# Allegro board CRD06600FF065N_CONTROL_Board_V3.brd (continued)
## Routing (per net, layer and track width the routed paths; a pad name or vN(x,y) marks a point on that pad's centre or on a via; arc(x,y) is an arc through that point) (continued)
P_SCL: length 26.7
  ART03 w0.127: v1(46.74,41.78) 46.74,41.66 47.12,41.27 48.51,41.27 48.86,40.93 61.43,40.93 62.86,39.5 v1(64.44,39.5)
  BOTTOM w0.152: U32.6 R438.1 64.7,37.98 64.44,38.23 v1(64.44,39.5) ; U28.174 47.22,39.51 47.32,39.62 47.32,41.2 v1(46.74,41.78)
P_SDA: length 23.4
  ART03 w0.127: v1(46.71,40.64) 46.71,40.41 47.12,40.01 49.02,40.01 49.27,40.25 60.5,40.25 63.5,37.26 v1(63.5,36.83)
  BOTTOM w0.152: U32.5 64.14,36.2 v1(63.5,36.83) R437.1 ; v1(46.71,40.64) U28.173
P_WD_GREEN: length 12.6
  BOTTOM w0.152: U28.143 31.71,40.54 33.05,41.87 35.96,41.87 36.96,42.87 39.86,42.87 40.34,43.35 D102.2
P_WD_RED: length 14.4
  BOTTOM w0.152: U28.144 32.22,40.26 33.34,41.38 36.18,41.38 37.25,42.44 41.96,42.44 42.87,43.35 D103.2
PFC-FB: length 4
  BOTTOM w0.152: J2.23 7.12,45.22 R49.2
PFC-VO: length 4.7
  TOP w0.152: R579.2 5.58,45.22 J2.24
PFC_OCP: length 20.3
  TOP w0.152: R605.2 19.56,40.26 17.27,40.26 R606.2 16.51,40.76 16.51,44.45 J2.15
  BOTTOM w0.152: J2.15 16.51,44.45 14.48,44.45 13.97,43.94 13.97,42.55 15.88,40.64 15.88,39.07 16.08,38.86 D96.3
PFCCURBSAMP: length 81.3
  TOP w0.152: R435.1 55.88,9.65 v1(56.39,10.16)
  ART03 w0.127: v1(56.39,10.16) 55.8,10.74 52.02,10.74 49.4,8.13 24.87,8.13 21.29,11.71 16.57,11.71 13.08,15.2 13.08,37.97 16.41,41.3 16.41,44.55 J2.17
PWM1A: length 54.5
  TOP w0.152: U58.8 63.5,30.48 v1(62.23,31.75)
  ART03 w0.127: J2.11 24.13,46.99 30.88,46.99 31.65,46.23 31.65,44.93 31.88,44.69 31.88,41.15 34.29,38.73 34.29,36.7 34.92,36.07 48.77,36.07 50.8,34.04 50.8,33.02 51.4,32.42 52.03,32.42 52.7,31.75 56.39,31.75 56.9,32.26 58.21,32.26 58.71,31.75 v1(62.23,31.75)
PWM1AA: length 20
  TOP w0.152: v1(62.23,33.02) 63.5,31.75 U58.9 ; v1(51.44,33.28) 51.93,33.78 52.7,33.78 53.47,33.02 R414.2
  ART03 w0.127: v1(51.44,33.28) 51.93,33.78 52.89,33.78 53.5,33.18 59.08,33.18 59.85,32.41 61.62,32.41 v1(62.23,33.02)
  BOTTOM w0.152: v1(51.44,33.28) U28.8
PWM1B: length 48.6
  TOP w0.152: U58.10 63.5,33.02 63.5,33.05 63.52,33.05 v1(63.52,33.06)
  ART03 w0.127: J2.5 31.62,44.58 31.62,40.26 32.95,38.93 32.95,36.54 34.44,35.05 48.9,35.05 50.29,33.66 50.29,31.88 51.05,31.11 57.66,31.11 58.8,29.97 62.53,29.97 63.52,30.96 v1(63.52,33.06)
PWM1BB: length 19.7
  TOP w0.152: U58.11 v1(63.5,34.29) ; v1(52.45,33.27) 52.7,33.27 54.23,31.75 R415.2
  ART03 w0.127: v1(63.5,34.29) 62.94,33.73 62.94,32.97 62.38,32.41 62.19,32.41 61.91,32.13 59.18,32.13 58.55,32.77 53.34,32.77 52.83,33.27 v1(52.45,33.27)
  BOTTOM w0.152: U28.10 51.08,32.28 51.56,32.77 51.94,32.77 v1(52.45,33.27)
PWM1C: length 57.4
  TOP w0.152: v1(63.35,19.2) 63.83,19.68 65.12,19.68
  ART03 w0.127: v1(58.55,29.08) 58.55,29.72 57.53,30.73 54.48,30.73 53.59,29.84 51.64,29.84 49.66,31.83 49.66,33.15 49.02,33.78 47.75,33.78 47.01,34.53 34.27,34.53 32.47,36.34 32.47,37.86 30.48,39.84 30.48,41.26 29.21,42.53 29.21,44.45 J2.7
  BOTTOM w0.152: v1(63.35,19.2) 63.35,20.09 62.69,20.75 61.85,20.75 61.63,20.97 60.59,20.97 59.45,22.11 59.45,24.54 58.83,25.17 58.83,28.93 58.55,29.21 v1(58.55,29.08)
PWM1CC: length 31.7
  TOP w0.152: v1(62.23,21.59) 62.36,21.46 63.37,21.46 63.88,20.95 U59.9 ; R416.2 v1(51.94,29.21)
  BOTTOM w0.152: U28.22 51.05,26.28 51.31,26.54 51.31,28.09 51.82,28.6 51.82,29.08 v1(51.94,29.21) 52.45,29.72 52.45,31.01 54.12,32.67 56.84,32.67 56.87,32.64 57.91,32.64 59.43,31.12 59.43,25.48 60.2,24.71 60.2,22.3 60.91,21.59 v1(62.23,21.59)
PWM1D: length 53.2
  TOP w0.152: U59.10 63.88,22.23 63.63,21.97 62.87,21.97 v1(62.23,22.61)
  ART03 w0.127: v1(62.23,22.61) 60.88,23.95 57.1,23.95 53.77,27.28 51.82,27.28 51.38,27.71 51.38,27.72 49.23,29.87 47.46,29.87 44.02,33.32 34.12,33.32 31.37,36.07 31.37,37.72 30.99,38.1 28.57,38.1 26.75,39.93 26.75,44.37 J2.9
PWM1DD: length 33.7
  TOP w0.152: v1(63.37,22.61) 63.37,23.01 63.86,23.5 U59.11 ; R417.2 v1(48.26,25.4)
  BOTTOM w0.152: v1(48.26,25.4) 48.65,25.79 U28.23 51.22,25.79 51.46,26.02 52.31,26.02 52.59,26.3 52.59,28.96 52.83,29.2 52.83,30.91 53.92,32 55.12,32 55.88,31.24 57.66,31.24 59.11,29.79 59.11,25.37 59.84,24.64 59.84,22.11 60.69,21.27 61.74,21.27 61.95,21.06 62.84,21.06 63.37,21.59 v1(63.37,22.61)
REF1: length 16.3
  TOP w0.152: R226.1 C262.2 70.48,12.06 v1(71.12,12.7)
  BOTTOM w0.152: U56.1 72.39,10.06 72.23,9.9 71.37,9.9 71.12,10.15 U56.2 v1(71.12,12.7) 70.23,13.59 67.08,13.59 66.69,13.2 U37.4 66.69,10.3 C268.2
RLYCTRL1: length 20.6
  BOTTOM w0.152: J2.22 10.16,39.88 11.3,38.73 15.29,38.73 16.05,37.97 18.8,37.97 19.68,38.86 D97.3 22.61,38.86 23.21,38.26 23.21,37.12 23.54,36.79 U28.132
SR-PWM-A: length 27.8
  TOP w0.152: v1(62.1,23.97) 62.23,23.97 63.03,24.77 U59.12
  ART03 w0.127: J3.9 67.56,43.18 70.5,40.24 70.5,38.88 64.79,33.17 64.79,26.18 63.41,24.81 62.94,24.81 v1(62.1,23.97)
SR-PWM-AA: length 34.2
  TOP w0.152: R422.2 53.53,31.43 53.53,31.69 v1(52.96,32.26) ; U59.13 63.72,26.04 v1(63.26,25.58)
  BOTTOM w0.152: v1(63.26,25.58) 62.81,25.13 62.81,22.43 62.48,22.1 60.88,22.1 60.58,22.4 60.58,24.82 59.78,25.61 59.78,31.4 58.17,33.02 53.34,33.02 52.96,32.64 v1(52.96,32.26) 52.83,32.38 51.82,32.38 51.31,31.88 51.31,28.57 51.02,28.28 U28.18
SR-PWM-B: length 27.7
  TOP w0.152: U59.2 60.96,26.04 v1(62.23,27.3)
  ART03 w0.127: J3.10 65.95,44.36 65.95,42.95 67.15,41.75 68.12,41.75 70.06,39.81 70.06,39.24 64.19,33.37 64.19,30.28 62.23,28.32 v1(62.23,27.3)
SR-PWM-BB: length 29.3
  TOP w0.152: U59.1 v1(61.09,27.3) ; v1(53.34,38.1) 53.34,38.02 54.49,36.88 R423.2
  BOTTOM w0.152: v1(61.09,27.3) 61.67,27.89 61.67,31.29 58.8,34.16 58.8,39.55 57.05,41.3 54.84,41.3 53.24,39.7 53.24,38.2 v1(53.34,38.1) 53.06,37.82 51.71,37.82 50.68,36.79 U28.1
SR-PWM-C: length 28.3
  TOP w0.152: v1(63.5,27.3) 63.5,26.8 61.21,24.51 61.21,24 60.71,23.5 U59.4
  BOTTOM w0.152: J3.11 69.85,43.17 68.35,41.67 63.5,41.67 62.49,40.66 62.49,37.67 62.81,37.35 62.81,28 v1(63.5,27.3)
SR-PWM-CC: length 25.2
  TOP w0.152: v1(52.07,35.18) 51.89,35.18 51,34.29 R424.2 ; v1(61.09,25.53) 61.09,25.15 60.71,24.77 U59.3
  BOTTOM w0.152: v1(61.09,25.53) 60.45,26.16 60.45,30.27 60.45,30.27 60.45,30.69 60.45,30.69 60.45,31.87 58.24,34.09 58.24,36.5 57.78,36.96 53.06,36.96 52.67,36.57 52.67,35.78 v1(52.07,35.18) 51.96,35.28 U28.4
SR-PWM-D: length 31.7
  TOP w0.152: v1(63.36,24) 62.72,23.37 62.1,23.37 61.72,22.99 61.72,21.72 60.96,20.95 U59.6
  ART03 w0.127: v1(63.36,24) 63.36,24.03 66.03,26.71 66.03,33.3 70.22,37.49 70.85,37.49 71.09,37.74 71.09,44.61 69.98,45.72 J3.12
SR-PWM-DD: length 23.4
  TOP w0.152: U59.5 60.71,22.23 v1(61.09,22.61) ; v1(53.34,34.04) 53.59,34.29 R425.2
  BOTTOM w0.152: v1(61.09,22.61) 61.09,24.77 60.11,25.75 60.11,31.59 58.33,33.37 54.01,33.37 v1(53.34,34.04) 53.18,34.2 51.09,34.2 51,34.28 U28.6
TCK_P: length 8.6
  TOP w0.152: R407.2 R408.2 33.66,9.02 33.05,9.63 33.05,10.36 32.64,10.77 30.64,10.77 v1(29.86,11.54)
  BOTTOM w0.152: U28.81 30.22,11.82 29.94,11.54 v1(29.86,11.54)
TDI_P: length 18.2
  TOP w0.152: J5.3 27.92,3.2 27.92,5.18 28.44,5.7 29.2,5.7 v1(29.84,6.35) R405.2
  BOTTOM w0.152: v1(29.84,6.35) 30.38,5.82 32.23,5.82 32.71,6.29 32.71,9.43 33.03,9.74 33.03,10.37 32.22,11.18 U28.77
TDO_P: length 13.9
  TOP w0.152: R406.2 32.38,6.99 v1(31.75,6.35) 33.01,5.09 33.01,3.19 J5.7
  BOTTOM w0.152: U28.78 31.71,6.39 v1(31.75,6.35)
TMS_P: length 15.7
  TOP w0.152: R404.2 v1(26.04,6.35) 25.18,5.5 25.18,3.39 J5.1
  BOTTOM w0.152: v1(26.04,6.35) 29.24,9.56 29.24,10.44 29.67,10.87 30.07,10.87 30.71,11.51 U28.80
VAC_POLARITY+: length 43.4
  TOP w0.152: v1(64.77,7.49) 62.99,9.27 62.99,11.18 60.93,13.23 60.93,17.12 61.98,18.16 61.98,18.92 v1(62.23,19.18)
  BOTTOM w0.152: v1(62.23,19.18) 62.23,19.3 61.87,19.66 61.87,20.27 61.48,20.66 60.44,20.66 59.11,22 59.11,24.46 58.55,25.02 58.55,27.43 57.91,28.07 57.91,30.35 57.4,30.86 55.5,30.86 55.24,31.11 D86.3 53.72,31.11 53.21,30.61 53.21,26.16 52.83,25.78 52.83,24 52.11,23.28 U28.28 ; U36.4 64.78,7.58 64.77,7.57 v1(64.77,7.49)
VO1+: length 10.5
  BOTTOM w0.508: J4.11 79.88,44.32 79.88,41.91 80.39,41.4 82.93,41.4 R574.1
VO2+: length 3.8
  TOP w0.508: R573.1 88.27,41.27 J4.8
VP3.3A: length 16.3
  TOP w0.381: C550.2 v1(43.81,15.24) ; C521.1 v1(48.26,19.05)
  BOTTOM w0.254: U28.36 48.49,19.28 v1(48.26,19.05) ; U28.54 43.71,15.14 v1(43.81,15.24)
  BOTTOM w0.508: v1(73.41,13.34) 74.04,12.7 74.04,7.92 72.98,6.86 R589.2 R225.1 ; R590.1 61.97,14.73 v1(61.85,14.61)
  vias: v1(59.56,10.79) v1(60.58,10.79)
VP3.3D: length 157.9
  TOP w0.381: C540.1 26.67,16.63 v1(26.67,16.51) ; 63.88,0.76 48.39,0.76 47.11,2.03 R412.1 R411.1 ; C541.2 v1(27.94,15.24)
  TOP w0.508: C547.2 v1(39.37,15.24) ; C545.2 v1(34.92,15.24) ; J18.2 20.95,8.29 v1(20.95,9.84) C406.2 ; R407.1 35.73,7.5 36.07,7.83 36.07,10.03 v1(36.2,10.16) ; C523.2 44.32,36.96 v1(44.2,36.83) ; C520.1 v1(48.26,35.56) ; C524.2 v1(40.01,36.83) ; C529.2 29.84,37.08 v1(29.59,36.83) ; R405.1 v1(29.84,10.16) ; C546.2 v1(36.83,15.24) ; R540.1 5.59,21.82 v1(5.43,21.66) ; R327.2 31.11,40.64 ; R409.2 v1(31.11,10.16) ; v1(21.97,26.54) 21.97,27.3 21.34,27.94 R546.2 20.57,27.3 v1(20.57,26.54) ; v1(48.26,24.13) 48.26,23.16 48.56,22.86 C557.2 ; v1(53.21,36.2) 53.21,37.16 52.57,37.8 52.57,38.59 53.35,39.37 54.58,39.37 ; C539.1 v1(26.67,20.32) ; R598.1 77.91,8.41 J17.2 ; v1(12.7,39.37) 13.46,38.61 R604.1 R606.1 ; C533.1 26.16,32.38 v1(26.67,32.89) ; R404.1 v1(26.04,10.16) ; C528.2 v1(33.66,36.83) ; C542.2 v1(29.84,15.24) ; C555.2 v1(48.26,27.94) ; R537.2 11.66,34.41 ; R400.2 37.47,40.64 ; C553.2 v1(48.26,30.48) ; C536.1 v1(26.67,28.57) ; C531.1 v1(26.67,34.92) ; C538.1 v1(26.67,23.5) ; C552.1 v1(48.26,31.75) ; v1(34.92,36.83) C527.2 ; C544.2 v1(33.66,15.24) ; C537.1 v1(26.67,27.3) ; R406.1 v1(32.38,10.16) ; C534.1 v1(26.67,31.11)
  BOTTOM w0.254: v1(33.66,36.83) 33.71,36.89 U28.147 ; U28.3 48.49,35.79 v1(48.26,35.56) ; U28.72 34.71,15.03 v1(34.92,15.24) ; v1(26.67,34.92) 26.03,34.28 U28.127 ; U28.11 48.3,31.79 v1(48.26,31.75) ; U28.106 26.38,23.79 v1(26.67,23.5) ; U28.119 26.22,30.28 26.67,30.73 v1(26.67,31.11) 26.04,31.11 25.71,30.79 U28.120 ; U28.125 26.28,33.28 v1(26.67,32.89) ; U28.138 29.22,37.21 v1(29.59,36.83) ; v1(26.67,27.3) 26.19,27.79 U28.114 ; U28.88 26.71,15.2 v1(26.67,15.24) ; v1(26.67,16.51) 26.44,16.28 U28.91 ; v1(44.2,36.83) 44.22,36.85 U28.168 ; v1(26.67,20.32) 26.63,20.28 U28.99 ; v1(36.83,15.24) 36.71,15.12 U28.68 ; v1(26.67,28.57) 26.46,28.79 U28.116 ; U28.20 48.92,27.28 v1(48.26,27.94) ; U28.152 36.22,37.82 35.23,36.83 v1(34.92,36.83) ; U28.62 39.71,14.9 v1(39.37,15.24) ; U28.75 33.22,14.8 v1(33.66,15.24) ; U28.26 48.41,24.28 v1(48.26,24.13) ; v1(48.26,30.48) 48.95,29.79 U28.15 ; U28.82 29.71,15.11 v1(29.84,15.24) ; U28.159 39.71,37.12 v1(40.01,36.83)
  BOTTOM w0.381: v1(53.21,36.2) 54.54,36.2 55.5,35.23 55.5,34.29 55.81,33.98 D94.2
  BOTTOM w0.508: C396.1 68.2,33.14 v1(68.07,33.27) 67.94,33.4 67.94,35.72 ; v1(71.75,34.8) R502.1 ; R437.2 v1(63.5,40.64) ; D96.2 13.92,39.81 v1(13.79,39.68) ; R438.2 v1(65.41,40.64) ; v1(49.53,44.45) 49.21,44.77 D98.2 ; D95.2 55.81,38.42 55.49,38.74 v1(55.49,39.35) ; R505.1 v1(71.12,33.02) ; R439.2 v1(67.31,40.64) ; J17.2 78.11,8.22 C405.1 ; D104.2 v1(52.7,41.91) ; v1(18.67,39.68) 18.8,39.81 D97.2
  vias: v1(6.35,11.43) v1(6.35,10.16) v1(6.35,8.89) v1(7.62,11.43) v1(7.62,10.16) v1(7.62,8.89) v1(27.94,16.51) v1(29.84,16.51) v1(49.53,43.18) v1(49.53,41.91) v1(51.44,41.91) v1(53.98,41.91) v1(71.75,1.27) v1(73.03,1.27) v1(74.3,1.27)
VP+5V: length 28
  TOP w0.381: C494.1 53.77,27.94 53.34,27.51 53.34,26.67 53.66,26.35 U55.1 56.7,26.35 58.55,28.19 68.45,28.19 v1(69.22,28.96) ; R549.2 v1(70.48,35.56)
  TOP w0.508: R536.2 9.01,30.86 v1(9.02,30.86) ; R550.2 69.34,28.83 v1(69.22,28.96)
  BOTTOM w0.381: R544.2 v1(40.01,6.35)
  BOTTOM w0.508: v1(69.22,28.96) 69.85,28.32 R595.2 70.87,28.06 71.38,28.57 R594.2
  vias: v1(6.1,32.77) v1(6.1,31.62) v1(6.1,30.48) v1(7.74,30.86) v1(10.29,30.86) v1(11.3,30.86) v1(52.7,5.08) v1(53.98,5.08) v1(53.98,3.81)
VP-5V: length 85.8
  ART03 w0.127: v1(69.85,19.3) 70.32,18.83 70.32,18.07 69.54,17.3 66.65,17.3 63.32,20.62 60.73,20.62 59.03,22.33 56.67,22.33 55.4,23.6 51,23.6 48.56,26.04 47.68,26.04 42.09,31.62 33.45,31.62 29.36,35.71 28.04,35.71 27.18,36.58 24,36.58 23.37,37.21 23.37,40.77 21.56,42.57 21.56,46.45 20.94,47.07 14.05,47.07 J2.19
  BOTTOM w0.152: U45.4 64.14,21.88 64.36,22.1 68.32,22.1 68.96,21.46 68.96,20.7 69.15,20.51 C450.1 v1(69.85,19.3)
VS+5V: length 7.3
  TOP w0.381: v1(98.3,23.75) 97.91,24.13 R492.2 ; v1(95.89,23.75) 95.89,23.4 95.61,23.12 R493.1 ; R496.1 v1(92.59,34.42)
  TOP w0.508: R507.1 v1(97.91,32.26)
  BOTTOM w0.381: R592.2 v1(88.9,20.95)
  BOTTOM w0.508: R593.2 91.87,26.04 v1(92.53,26.7)
VS+15V: length 24.8
  ART03 w0.508: v1(92.71,32.38) 91.44,32.38 88.9,34.92 v1(88.9,35.56) 91.44,38.1 v1(91.56,38.1) 92.94,38.1 95.29,40.45 95.29,44.41 J4.1
  BOTTOM w0.508: R503.1 91.69,32.89 92.2,32.89 v1(92.71,32.38) ; R569.1 v1(88.9,35.56) ; R597.1 v1(91.56,38.1) R500.1
VS+15V_U48: length 16.6
  ART03 w0.508: v1(90.17,38.1) 89.92,38.1 88.14,36.32 88.14,30.48 v1(88.9,29.72)
  BOTTOM w0.508: v1(90.17,38.1) 90.05,38.22 R597.2 ; U48.8 93.34,29.72 93.09,29.46 92.08,29.46 91.44,30.1 C566.1 C462.1 89.28,30.1 v1(88.9,29.72)
X1: length 9.1
  BOTTOM w0.254: Y1.1 17.62,33.08 20.13,33.08 C371.2 21.2,32.9 R221.1 21.82,32.28 U28.123
X2: length 9.3
  BOTTOM w0.254: Y1.2 18.44,31.24 C254.2 21.34,31.24 R221.2 21.64,30.99 21.94,31.28 U28.121
XRS: length 28
  TOP w0.508: v1(21.72,33.78) 21.71,33.78 C519.1 21.71,31.24 R546.1 20.1,30.74 19.82,30.46 19.82,27.43 15.89,23.5 R541.1 10.29,23.5 10.29,24.43 11.18,25.32 11.18,27.74 10.92,28 R547.1
  BOTTOM w0.254: v1(21.72,33.78) 22.35,33.15 23.37,33.15 23.73,32.79 U28.124
N16777869: length 10.1
  TOP w0.152: J5.11 J5.9 35.54,3.19 35.54,5.41 35.24,5.71 34.04,5.71 33.66,6.1 R408.1
N16779815: length 3.6
  TOP w0.152: v1(30.66,36.83) 31.11,37.29 R327.1
  BOTTOM w0.152: v1(30.66,36.83) 29.71,37.77 U28.139
N16809513: length 6.4
  TOP w0.152: J5.5 30.5,3.15 30.5,6.3 31.11,6.91 R409.1
N16810933: length 3.9
  TOP w0.152: R412.2 42.55,2.54 J5.13
N16810951: length 3.9
  TOP w0.152: J5.14 42.55,3.81 R411.2
N16824215: length 5.1
  TOP w0.152: R436.1 R435.2 R433.2 R434.1 C395.1
N16833081: length 2
  BOTTOM w0.152: R443.1 39.71,45.55 D102.1
N16833084: length 2
  BOTTOM w0.152: R444.1 44.16,45.21 D103.1
N16833087: length 2
  BOTTOM w0.152: D104.1 52.36,45.21 R445.1
N16835391: length 24.3
  TOP w0.152: v1(61.85,13.46) 61.85,12.95 63.5,11.3 63.5,9.53 64.77,8.26 J17.1
  BOTTOM w0.152: J17.1 C407.1 R446.1 ; R447.1 v1(61.85,13.46)
N16836592: length 57.5
  TOP w0.152: v1(27.94,17.78) 27.26,17.1 27.26,17.09 27.26,16.12 26.91,15.78 25.63,15.78 24.7,14.85 18.26,14.85 17.45,14.03 17.45,11.61 17.75,11.31 C409.1 R448.1 19.68,9.53 J18.1
  ART03 w0.127: v1(61.09,18.41) 59.87,18.41 57.91,20.37 49.63,20.37 49.31,20.69 46.49,20.69 44.32,18.52 28.68,18.52 v1(27.94,17.78)
  BOTTOM w0.152: R449.1 v1(61.09,18.41)
N16848574: length 4
  BOTTOM w0.381: U43.2 R482.2 C446.1
N16848598: length 4.6
  BOTTOM w0.381: R593.1 C445.2 89.41,27.3 88.14,26.04 U43.1
N16848614: length 6.9
  TOP w0.508: v1(74.93,25.4) 75.44,24.89 C447.2
  BOTTOM w0.381: v1(74.93,25.4) 75.56,26.04 75.82,26.04 ; 75.82,26.04 U43.8 ; 75.82,26.04 75.69,26.16 75.69,26.92 74.04,28.57 R594.1
N16848642: length 2.8
  BOTTOM w0.152: R483.1 U43.7
N16848644: length 12.7
  TOP w0.152: v1(71.12,23.62) 70.99,23.62 v1(66.8,19.43)
  BOTTOM w0.152: v1(71.12,23.62) 72.26,24.77 R483.2 R484.2 C448.2 ; v1(66.8,19.43) 65.91,19.43 65.41,19.94 U45.3
N16848814: length 2.8
  BOTTOM w0.152: 76.54,23.5 R485.1
N16848816: length 10.7
  TOP w0.152: v1(71.12,22.61) 71,22.48 C449.1 70.74,20.45 68.85,20.45 v1(67.77,19.37)
  BOTTOM w0.152: U45.2 66.67,20.17 66.86,19.98 67.16,19.98 v1(67.77,19.37) ; R485.2 72.26,23.5 71.37,22.61 v1(71.12,22.61) R486.1
N16848832: length 38.8
  TOP w0.152: v1(73.66,19.05) 72.52,20.19 C449.2 ; v1(57.63,12.04) 57.63,13.16 57,13.79 56.82,13.79 R487.1
  ART03 w0.127: v1(57.63,12.04) 57.63,10.97 58.45,10.16 60.93,10.16 61.95,11.18 72.85,11.18 74.83,13.16 74.83,17.88 v1(73.66,19.05)
  BOTTOM w0.152: 67.94,20.79 67.94,20.19 69.34,18.8 70.33,18.8 71.12,19.58 R486.2 72.51,20.2 v1(73.66,19.05)
N16848970: length 3.4
  BOTTOM w0.152: U44.6 96.52,20.5 96.22,20.19 95.5,20.19 95.25,20.45 U44.7
N16848978: length 9.7
  TOP w0.152: C454.1 R488.2 C453.2 R489.2 R492.1 96.4,24.25 v1(96.9,23.75)
  BOTTOM w0.152: U44.3 96.52,24.03 96.8,23.75 v1(96.9,23.75)
N16848994: length 10.6
  TOP w0.152: R494.2 93.07,24.64 v1(92.71,24.99) 91.97,24.25 R491.1 C455.1 ; R494.2 93.47,24.76 C454.2 ; R494.2 R493.2
  BOTTOM w0.152: U44.2 95.25,25.66 94.59,24.99 v1(92.71,24.99)
N16849016: length 4.4
  BOTTOM w0.152: U44.8 93.98,22.07 93.83,22.23 C457.1 R592.1
N16851028: length 3.3
  BOTTOM w0.152: U45.6 65.41,27.15 65.56,27.3 66.52,27.3 66.67,27.15 U45.7
N16851046: length 4.3
  BOTTOM w0.152: C451.1 R595.1 69.21,26.55 68.83,26.92 68.2,26.92 67.94,26.67 67.94,26.2
N16853569: length 5.3
  TOP w0.152: v1(95.89,34.29) 95.76,34.41 R495.2 C458.1 C460.1
  BOTTOM w0.152: U48.3 v1(95.89,34.29)
N16853931: length 10.1
  TOP w0.152: v1(94.61,34.29) 94.1,34.8 R496.2 C459.1 R497.1 94.1,38.66 94.51,39.07 96.82,39.07 97.28,38.61 C460.2
  BOTTOM w0.152: U48.2 v1(94.61,34.29)
N16853972: length 4.8
  BOTTOM w0.152: U48.1 93.34,34.42 92.71,33.78 92.07,33.78 R499.1 R569.2
N16854569: length 3.4
  BOTTOM w0.152: R500.2 89.03,36.83 88.39,36.2 U60.1
N16855013: length 10
  TOP w0.152: C466.2 93.85,31.49 93.85,31.88 94.74,32.77 95.89,32.77 v1(96.39,32.26) 96.4,32.26 R507.2 C467.1 R508.1
  BOTTOM w0.152: U48.5 97.16,31.5 v1(96.39,32.26)
N16855828: length 6
  TOP w0.152: v1(95.38,32.26) 94.99,31.87 C466.1 C465.1 R506.2
  BOTTOM w0.152: v1(95.38,32.26) 95.89,31.75 U48.6
N16855912: length 3.5
  BOTTOM w0.152: U61.2 87.86,28.57 88.29,28.14 89.61,28.14 R510.2
N16855916: length 3.9
  BOTTOM w0.152: U61.1 88.14,31.11 R503.2
N16860426: length 79.7
  TOP w0.152: C472.1 R598.2 ; C472.1 C471.1 ; C472.1 75.63,12.7 v1(75.25,12.32)
  ART03 w0.127: v1(75.25,12.32) 73.75,10.82 62.18,10.82 61.21,9.86 58.37,9.86 56.79,11.43 52.07,11.43 51.56,10.92 50.29,10.92 49.12,12.09 48.26,12.09 45.69,9.53 25.91,9.53 21.97,13.46 21.97,13.97 18.29,17.65 18.29,23.37 v1(19.05,24.13)
  BOTTOM w0.152: U53.1 75.44,11.43 75.25,11.62 v1(75.25,12.32) ; v1(19.05,24.13) R514.1 R515.1
N16860580: length 10.1
  TOP w0.508: C473.1 C475.1 C474.1 R516.2 90.32,12.04 90.83,12.04 91.31,11.56 v1(91.44,11.56)
  BOTTOM w0.508: v1(91.44,11.56) 91.31,11.43 U53.8
N16860640: length 9.7
  TOP w0.152: v1(84.45,13.97) 85.72,15.24 D112.1 D110.2
  BOTTOM w0.152: T1.2 U53.7 v1(84.45,13.97)
N16861242: length 8.5
  BOTTOM w0.152: T1.3 97.24,13.97 94.74,11.47 R517.1 94.74,8.73 J11.2
N16861249: length 9.2
  TOP w0.152: D113.2 D114.1 v1(84.45,16.51)
  BOTTOM w0.152: T1.1 U53.6 v1(84.45,16.51)
N16861268: length 11.3
  BOTTOM w0.152: J11.1 93.22,8.77 R517.2 93.22,11.89 97.84,16.51 T1.4
N16861373: length 4.3
  TOP w0.381: D111.2 90.77,14.61 90.3,14.61 89.66,15.24 D112.2 D114.2
N16866679: length 36.2
  TOP w0.152: R528.1 C488.1 R58.2 R600.1 50.16,12.06 v1(50.8,11.43)
  ART03 w0.127: v1(57.15,19.68) 57.07,19.61 46.28,19.61 44.45,17.78 43.18,17.78 41.4,16 41.4,13.97 42.8,12.58 49.65,12.58 v1(50.8,11.43)
  BOTTOM w0.152: R529.1 56.13,19.68 v1(57.15,19.68)
N16866735: length 5.1
  TOP w0.152: R531.1 R578.2 R530.1 C490.1 R601.1
N16867200: length 4.5
  TOP w0.152: R532.2 C492.1 R533.1 56.52,20.2 R534.1
N16867335: length 3.2
  TOP w0.152: R532.1 53.34,22.98 53.14,23.19 53.14,24.23 53.36,24.45 U55.2
N16868074: length 5.2
  TOP w0.152: R230.2 C264.1 ; R230.2 R229.2 ; R230.2 v1(64.14,11.81)
  BOTTOM w0.152: U36.2 v1(64.14,11.81)
N16868076: length 2.6
  TOP w0.152: R229.1 65.41,15.24 v1(64.77,15.88)
  BOTTOM w0.152: v1(64.77,15.88) 65.39,15.25 U37.1
N16868126: length 5.9
  BOTTOM w0.381: U36.5 63.49,7.51 63.5,7.49 63.5,6.47 R591.1 62.48,6.35 61.59,7.24 C265.2
N16868143: length 11.6
  TOP w0.508: C266.2 72.51,13.46 v1(73.66,14.61)
  BOTTOM w0.381: U56.8 72.39,16.13 73.66,14.86 v1(73.66,14.61) 72.77,13.72 72.77,12.95 73.28,12.45 73.28,9.27 72.39,8.38 R589.1
N16868206: length 10.2
  TOP w0.152: C495.2 71,16.36 70.26,15.62 R602.2 69.85,14.78 70.03,14.61 v1(71.12,14.61) 71.5,14.61 72.01,15.11 R535.1
  BOTTOM w0.152: U56.6 69.85,16.13 71.12,14.86 v1(71.12,14.61)
N16868218: length 18.5
  TOP w0.152: v1(72.39,14.61) 72.77,14.99 72.77,16.86 72.49,17.14 R535.2 72.01,18.16 C495.1
  BOTTOM w0.152: U56.7 71.12,16.15 72.39,14.88 v1(72.39,14.61) 71.84,14.06 67.38,14.06 66.69,14.74 U37.3 66.69,15.25 67.44,16 67.44,18.16 67.19,18.41 R524.1
N16868269: length 7.6
  TOP w0.152: R226.2 C262.1 67.82,14.48 v1(67.94,14.61) 67.94,14.99 R603.2
  BOTTOM w0.152: v1(67.94,14.61) 68.58,15.24 U56.5
N16868287: length 5.3
  BOTTOM w0.152: R225.2 C267.2 ; C267.2 R224.1 ; C267.2 U56.3
N16900365: length 4.1
  TOP w0.508: R537.1 R538.2 8.76,32.9 7.93,33.72 Q1.1
N16900541: length 7.3
  TOP w0.508: v1(8.4,27.46) 8.4,27.92 C505.1 7.5,28.82 R536.1 6.99,30.36 Q1.3
  BOTTOM w0.381: v1(8.4,27.46) 8.58,27.64 U57.7
N16908509: length 4.6
  TOP w0.508: v1(7.75,24.51) 7.41,24.51 7.11,24.2 R540.2 R541.2
  BOTTOM w0.381: v1(7.75,24.51) 7.93,24.33 U57.19
N16911091: length 2.6
  BOTTOM w0.508: U37.5 64.88,12.97 64.64,13.21 C263.2 R590.2
N16917336: length 18.7
  BOTTOM w0.152: R525.1 57.78,27.43 58.27,26.95 58.27,24.81 58.83,24.26 58.83,21.82 60.26,20.38 61.3,20.38 61.59,20.09 61.59,19.09 62.02,18.67 64.14,18.67 64.89,17.91 C483.1 65.15,17.14 65.4,16.89 65.41,16.89 R524.2
N16935004: length 2.7
  TOP w0.508: v1(9.41,27.47) 9.4,27.48 R547.2
  BOTTOM w0.381: v1(9.41,27.47) 9.23,27.65 U57.8
N16936023: length 9.3
  BOTTOM w0.152: U28.59 41.22,11.37 40.58,10.73 40.58,9.59 R544.1 C518.1 38.73,9.04 37.95,9.82 ZD3.2 37,9.82 R545.2
N17022031: length 6.6
  TOP w0.152: C561.1 R549.1 C562.1 C560.1 U58.14
N17025421: length 6.5
  TOP w0.152: C564.1 C565.1 C563.1 R550.1 U59.14
N17045637: length 3.4
  BOTTOM w0.152: R499.2 89.03,34.29 88.39,33.66 86.94,33.66
N17046827: length 4.5
  BOTTOM w0.152: R510.1 94.11,28.57 94.61,29.08 U48.7
N17096901: length 14.1
  TOP w0.381: R488.1 93.46,27.32 91.55,27.32 C237.2 R133.1 90.14,27.4 90.14,35.46 R573.2
N17102058: length 27.9
  TOP w0.152: R506.1 92.86,28.57 91.85,29.59 91.85,32.44 92.86,33.45 96.06,33.45 96.52,33.91 96.52,34.08 96.52,34.08 96.52,34.67 96.93,35.08 96.93,35.21 R495.1 v1(98.42,35.56)
  BOTTOM w0.152: R574.2 87.76,39.4 88.87,40.51 93.09,40.51 94.99,38.61 C594.1 R575.1 97.69,38.61 97.92,38.38 97.92,36.07 v1(98.42,35.56)
N17145225: length 8.6
  BOTTOM w0.152: R599.2 44.45,7.5 44.9,7.94 44.9,8.19 C595.1 45.08,9.65 44.87,9.65 44.45,10.08 44.45,10.41 44.2,10.67 43.81,10.67 43.18,11.3 43.18,11.94 42.71,12.4 U28.56
N17156215: length 75.3
  TOP w0.152: v1(38.73,6.35) 38.73,8.13 39.62,9.01 R601.2 ; v1(5.71,41.91) 5.21,42.41 R579.1
  ART03 w0.127: v1(5.71,41.91) 8.38,41.91 8.89,42.42 8.89,43.56 9.58,44.25 13.51,44.25 13.98,43.78 13.98,40.61 13.23,39.86 13.23,38.94 12.7,38.42 12.7,14.89 16.48,11.11 21.03,11.11 24.52,7.62 37.47,7.62 v1(38.73,6.35)
N17156241: length 92
  TOP w0.152: v1(48.84,11.58) 48.84,13.56 49.38,14.09 R600.2
  ART03 w0.127: v1(5.71,43.18) 7.17,44.63 13.39,44.63 13.97,45.21 13.97,46.1 14.68,46.81 18.21,46.81 18.92,46.1 18.92,41.53 13.84,36.45 13.84,16.76 17.65,12.95 21.46,12.95 25.4,9.02 45.77,9.02 48.34,11.58 v1(48.84,11.58)
  BOTTOM w0.152: v1(5.71,43.18) 4.95,42.41 R49.1
N17158559: length 52.1
  TOP w0.152: v1(27.43,37.47) 27.3,37.33 R16.2 ; R603.1 68.2,18.03 v1(68.2,18.29)
  ART03 w0.127: v1(68.2,18.29) 67.14,18.29 63.34,22.09 60.57,22.09 58.98,23.67 56.67,23.67 54.33,26.01 51.66,26.01 49.05,28.62 47.34,28.62 43.21,32.76 33.92,32.76 30.1,36.58 30.1,37.21 29.84,37.47 v1(27.43,37.47)
N17158583: length 56.6
  TOP w0.152: R572.2 24.13,37.33 v1(24.38,37.59) ; R602.1 69.85,18.03 v1(69.6,18.29)
  ART03 w0.127: v1(24.38,37.59) 25.02,36.96 27.43,36.96 28.18,36.21 29.71,36.21 33.7,32.22 42.55,32.22 47.41,27.36 48.66,27.36 51.94,24.08 55.55,24.08 57,22.63 59.46,22.63 61.09,21.01 63.7,21.01 67.06,17.65 68.96,17.65 v1(69.6,18.29)
N16779431153: length 3.1
  TOP w0.152: R400.1 v1(37.47,36.83)
  BOTTOM w0.152: v1(37.47,36.83) 37.22,37.08 U28.154

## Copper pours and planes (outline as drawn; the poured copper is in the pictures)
AGND on TOP (solid shape): 72.03,9.87 72.03,8.89 71.73,8.59 64.93,8.59 64.39,9.13 64.39,9.91 64.64,10.16 71.74,10.16
AGND on TOP (solid shape): 72.03,7.75 72.03,6.84 71.61,6.42 66.36,6.42 65.79,6.99 65.79,7.62 65.79,7.62 65.79,7.87 65.84,7.92 71.86,7.92
AGND on TOP (solid shape): 43.45,29.63 43.45,24.1 41.65,22.3 38.9,22.3 37.89,21.29 33.32,21.29 31.64,22.97 31.64,31.9 32.32,32.58 40.5,32.58
AGND on TOP (solid shape): 14.89,15.06 14.89,10.29 15.4,9.78 15.4,3.67 15.37,3.64 15.37,1.09 14.85,0.57 0.93,0.57 0.59,0.91 0.59,11.42 0.95,11.78 3.91,11.78 4.24,11.45 4.24,8.37 3.8,7.93 2.32,7.93 1.47,7.08 1.47,2.91 2.42,1.97 10.44,1.97 11.73,3.25 11.73,15.06 12.1,15.43 14.52,15.43
AGND on TOP (solid shape): outline of 190 points within 11.83,24.07 23.18,37.72
AGND on BOTTOM (solid shape): 43.19,31.06 43.19,21.89 42.1,20.8 32.22,20.8 31.23,21.79 31.23,31.28 31.85,31.9 42.35,31.9
AGND on BOTTOM (solid shape): 53.94,2.79 53.94,0.69 53.81,0.56 45.01,0.56 44.86,0.71 44.86,1.77 45.02,1.93 48.44,1.93 48.86,1.51 52.06,1.51 52.39,1.84 52.39,2.83 52.53,2.97 53.76,2.97
AGND on BOTTOM (solid shape): 61.82,2.52 65.34,2.52 65.68,2.86 70.05,2.86 70.24,2.66 70.24,1.12 69.94,0.82 56.94,0.82 56.65,1.11 56.65,2.28 56.87,2.5 58.86,2.5 59.22,2.86 61.48,2.86
AGND on BOTTOM (solid shape): 82.1,19.81 82.1,0.85 81.82,0.57 75.45,0.57 75.26,0.76 75.26,1.38 75.55,1.66 78.71,1.66 79.62,2.57 79.62,10.76 78.92,11.46 78.92,19.73 79.18,19.99 81.92,19.99
AGND on BOTTOM (solid shape): 34.04,47.12 34.04,45.21 33.78,44.96 32.2,44.96 31.93,45.22 31.93,46.47 31.54,46.86 17.72,46.86 11.94,46.86 11.3,46.23 11.3,45.34 10.92,44.96 8.93,44.96 9.1,46.04 8.49,46.96 8.49,47.5 33.66,47.5
AGND on BOTTOM (solid shape): outline of 197 points within 0.51,3.81 23.39,38.4
AGND on ART02 (solid shape): outline of 15802 points within 0.57,0.52 81.27,47.44
AGND on ART03 (solid shape): 47.41,25.82 47.41,23.79 44.58,20.95 44.61,20.95 43.63,19.98 30.48,19.98 29.8,20.66 29.8,30.38 30.36,30.94 42.29,30.94
AGND on ART03 (solid shape): outline of 186 points within 14.5,13.3 21.4,37.59
AGND on ART03 (solid shape): outline of 701 points within 31.96,38.01 65.66,47.44
DGND on TOP (solid shape): outline of 664 points within 82.67,19.97 99.44,47.45
DGND on BOTTOM (solid shape): outline of 742 points within 82.89,22.39 99.43,47.45
DGND on ART02 (solid shape): outline of 1655 points within 82.93,19.94 99.44,47.5
VDD on TOP (solid shape): outline of 329 points within 7.66,3.28 48.45,37.21
VDD on BOTTOM (solid shape): 10.12,23.98 10.29,23.95 10.46,23.98 11.21,23.98 11.37,23.82 11.37,21.29 10.73,20.65 10.73,6.14 11.07,5.8 11.07,4.09 10.88,3.9 7.96,3.9 7.81,4.05 7.81,5.82 8.89,6.9 8.89,21.15 9.7,21.96 9.7,23.75 9.92,23.98
CAN5V_GND on TOP (solid shape): outline of 111 points within 85.98,0.55 99.49,19.4
CAN5V_GND on BOTTOM (solid shape): 99.4,11.84 99.4,1.04 98.87,0.51 90.15,0.51 89.49,1.17 89.49,7.37 88.72,8.15 86.32,8.15 85.98,8.48 85.98,10.21 86.32,10.55 90.37,10.55 91.47,9.44 91.47,7.19 91.77,6.9 96.23,6.9 96.53,7.19 96.53,11.86 96.76,12.08 99.16,12.08
CAN5V_GND on ART02 (solid shape): outline of 296 points within 83.4,0.56 99.49,19.43
CAN5V_GND on ART03 (solid shape): outline of 213 points within 83.41,0.59 99.4,19.38
P_ADREF3.2V on TOP (solid shape): outline of 753 points within 42.46,1.32 62.48,21.41
P_ADREF3.2V on BOTTOM (solid shape): 51.75,5.32 51.75,2.16 51.63,2.03 49.24,2.03 48.61,2.66 48.61,5.37 48.73,5.49 51.59,5.49
VP3.3A on BOTTOM (solid shape): 60.85,11.03 60.85,7.34 62.98,5.21 62.98,3.23 62.87,3.13 61.93,3.13 61.5,3.55 58.99,3.55 58.67,3.86 56.57,3.86 56.36,4.07 56.36,5.08 56.75,5.46 59.03,5.46 59.43,5.86 59.43,8.26 59.44,8.26 59.44,8.51 59.18,8.76 59.18,11.05 59.31,11.18 60.69,11.18
VP3.3A on ART03 (solid shape): outline of 1204 points within 43.31,10.48 74.51,19.24
VP3.3D on TOP (solid shape): outline of 1055 points within 49.15,0.63 78.83,44.7
VP3.3D on TOP (solid shape): outline of 1843 points within 0.56,8.13 37.86,47.28
VP3.3D on BOTTOM (solid shape): 66.9,6 74.4,6 74.68,5.72 74.68,1.08 74.5,0.9 70.89,0.9 70.74,1.05 70.74,3.02 70.27,3.49 65.6,3.49 65.25,3.14 64.11,3.14 64.03,3.21 64.03,4.32 64.52,4.8 64.52,6.6 64.64,6.73 66.17,6.73
VP3.3D on BOTTOM (solid shape): outline of 282 points within 1.02,0.69 54.29,44.7
VP3.3D on ART03 (solid shape): outline of 1356 points within 18.29,9.84 40.24,40.51
VP+5V on BOTTOM (solid shape): 54.57,5.33 54.57,3.68 54.28,3.4 52.5,3.4 52.49,3.41 52.49,5.33 52.59,5.43 54.47,5.43
VP+5V on BOTTOM (solid shape): 12.06,32.94 12.23,32.94 12.38,32.79 12.38,31.72 12.38,31.71 12.38,31.08 11.38,30.08 11.38,28.27 11.21,28.1 10.53,28.1 10.35,28.27 10.35,30.2 9.99,30.56 6.5,30.56 6.16,30.21 6.16,28.21 6.1,28.15 5.24,28.15 5.15,28.24 5.15,30.23 4.83,30.56 2.9,30.56 2.69,30.76 2.69,32.61 3.03,32.95 12.05,32.95
VP+5V on ART03 (solid shape): outline of 7089 points within 0.86,0.54 82.23,43.93
VS+5V on ART03 (solid shape): outline of 833 points within 85.02,20.33 99.42,47.47
N16830570 on BOTTOM (solid shape): 47.92,5.33 47.92,2.88 47.71,2.66 45.17,2.66 44.81,3.03 44.81,5.08 45.19,5.46 47.8,5.46

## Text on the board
BOTTOM: ARTWORK BOTTOM
Board Geometry/Soldermask Bottom: SOLDERMASK BOTTOM
Package Geometry/Pastemask Bottom: PASTEMASK BOTTOM
Ref Des/Silkscreen Bottom: A | SILKSCREEN BOTTOM
TOP: ARTWORK TOP
Board Geometry/Soldermask Top: SOLDERMASK TOP
Package Geometry/Pastemask Top: PASTEMASK TOP
Ref Des/Silkscreen Top: B | A1 | A | REV 3 1919 | CRD06600FF065N Control Board | SILKSCREEN TOP
ART02: ARTWORK LAYER02
ART03: ARTWORK LAYER03
DIMENSION: Board Cut Out | V-cut | FAB DRAWING
ASSEMBLY_TOP: PRIMARY SIDE
ASSEMBLY_BOTTOM: SECONDARY SIDE
User.7: ARTWORK LAYER03
User.9: ARTWORK LAYER02
User.21: FIGURE | SIZE | 12.0 | 32.0 | 35.0 | 39.0 | 45.0 | DRILL CHART: TOP to BOTTOM | ALL UNITS ARE IN MILS | PLATED | QTY | 498 | 2 | 6 | 48 | 14
